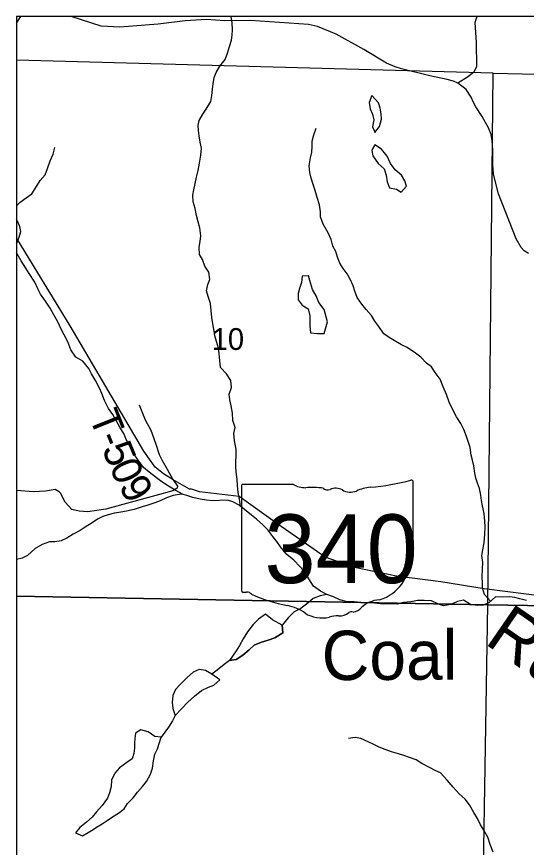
# Model space of a CAD drawing. Extents: x -452339 to 6403467, y -1 to 1814750.
# Drawn here: x -75201 to -70035, y 1554727 to 1563141 of the extents above; entities that cross this region are included whole.
import ezdxf

# ---------------------------------------------------------------- set-up
doc = ezdxf.new("R2010")
doc.units = 0
for name, color, linetype in [('Default', 7, 'Continuous'), ('GM_X_Corporation', 7, 'Continuous'), ('GM_X_County_Road', 7, 'Continuous'), ('GM_X_County_ROW', 7, 'Continuous'), ('GM_X_Major_Lake', 7, 'Continuous'), ('GM_X_Major_Lake_Text', 7, 'Continuous'), ('GM_X_Major_River_Text', 7, 'Continuous'), ('GM_X_Section_Text', 7, 'Continuous'), ('GM_X_Township_Road', 7, 'Continuous'), ('GM_X_Township_Road_Text', 7, 'Continuous'), ('GM_X_Unincorporated_Location', 7, 'Continuous')]:
    doc.layers.add(name, color=color, linetype=linetype)

msp = doc.modelspace()

# ---------------------------------------------------------------- linework, layer by layer
at = {"layer": 'Default'}
msp.add_lwpolyline([(-73615.1, 1558449.2), (-73570.7, 1558383.8), (-73572.9, 1558365.8), (-73619.2, 1558338.3), (-73789.7, 1558290.2), (-74050.5, 1558219), (-74295.2, 1558151.8), (-74479.5, 1558125.8), (-74567.4, 1558132.9), (-74641.2, 1558147.7), (-74708.3, 1558222.6), (-74755.3, 1558313.3), (-74769.1, 1558327.5), (-74808.8, 1558350), (-74907, 1558335.1), (-75031.1, 1558326.5), (-75200.9, 1558340.5)], dxfattribs=at)
at = {"layer": 'GM_X_County_Road'}
msp.add_line((-75200.9, 1563075.2), (-75158.8, 1563140.5), dxfattribs=at)
msp.add_lwpolyline([(-69611, 1557238.6), (-70462.9, 1557344.8), (-70901.9, 1557416.9), (-71352.9, 1557474.9), (-71776, 1557561.2), (-72072.9, 1557666.1), (-72553.3, 1558000.6), (-72946.4, 1558281.7), (-73174.2, 1558307.7), (-73347.2, 1558329.2), (-73429.2, 1558353.2), (-73447.7, 1558354), (-73615.1, 1558449.2), (-73713.1, 1558511.2), (-73797.3, 1558577.5), (-73913.1, 1558739.5), (-74659.5, 1560008.5), (-75200.9, 1560899.1)], dxfattribs=at)
at = {"layer": 'GM_X_County_ROW'}
for points in [[(-70015, 1560741.7), (-70057.1, 1560767.5), (-70089.3, 1560801.3), (-70138, 1560891.1), (-70317.1, 1561346.5), (-70352, 1561478.4), (-70368.5, 1561548.4), (-70375.1, 1561636.5), (-70374.2, 1561788.8), (-70382.9, 1561882.9), (-70393.3, 1561946.9), (-70419.8, 1562012.8), (-70482.6, 1562128.5), (-70547.3, 1562228.2), (-70571.6, 1562272.1), (-70595.9, 1562324), (-70646.4, 1562401.7), (-70674.6, 1562427.5), (-70730.9, 1562467.1), (-70773, 1562486.8), (-70839.1, 1562504.3), (-71015.3, 1562541), (-71301.6, 1562610.9), (-71365.7, 1562630.4), (-71452, 1562669.8), (-71682.8, 1562806.2), (-71963.8, 1562962.3), (-72153.6, 1563038.8), (-72244.3, 1563059), (-72831.9, 1563100.5), (-73095.7, 1563098.3), (-73275.6, 1563112.1), (-73491.5, 1563097.9), (-73767.3, 1563065.7), (-74155, 1563033.3), (-74342.9, 1563045.1), (-74648.1, 1563140.5)], [(-70531, 1563140.5), (-70539.6, 1563131.7), (-70559.3, 1563079.4), (-70545.8, 1562877.2), (-70540.1, 1562634.9), (-70567.7, 1562578.6), (-70631.3, 1562528), (-70730.9, 1562467.1)], [(-73615.1, 1558449.2), (-73671.1, 1558553.3), (-73723.1, 1558643.4), (-73753.1, 1558703.5), (-73791.2, 1558817.6), (-73837.2, 1558949.8), (-73895.2, 1559053.9), (-73957.3, 1559204.1)]]:
    msp.add_lwpolyline(points, dxfattribs=at)
at = {"layer": 'GM_X_Major_River_Text'}
for points in [[(-71602, 1562342), (-71627.8, 1562269.8), (-71617.6, 1562207.8), (-71593.4, 1562151.8), (-71581.2, 1562095.8), (-71595, 1562023.7), (-71578.9, 1561986.4)], [(-71578.9, 1561986.4), (-71570.9, 1561967.7), (-71523.1, 1562027.9), (-71503.3, 1562102.1), (-71505.5, 1562156.1), (-71515.6, 1562212.1), (-71533.8, 1562268.1), (-71602, 1562342)], [(-71593.3, 1561800.8), (-71602.3, 1561783.3), (-71590.1, 1561729.3), (-71537.9, 1561651.4), (-71475.8, 1561599.6), (-71455.6, 1561533.6), (-71447.4, 1561467.5), (-71423.2, 1561405.5), (-71353.2, 1561393.7), (-71303.1, 1561363.9)], [(-71303.1, 1561363.9), (-71249.3, 1561422.1), (-71267.5, 1561478.1), (-71301.7, 1561536.1), (-71365.8, 1561589.9), (-71412, 1561651.8), (-71446.2, 1561725.8), (-71504.4, 1561799.7), (-71572.5, 1561841.5), (-71593.3, 1561800.8)], [(-72085.4, 1560174), (-72138.7, 1560244.5), (-72167.1, 1560312.4), (-72201.5, 1560378.2), (-72221.9, 1560444.1), (-72244.4, 1560514), (-72308.3, 1560513.6), (-72315.8, 1560449.5), (-72333.4, 1560387.3), (-72347, 1560337.2), (-72346.5, 1560271.1), (-72308.2, 1560217.3), (-72248, 1560179.7), (-72229.6, 1560111.8), (-72229.2, 1560057.7), (-72230.9, 1560007.7), (-72224.4, 1559939.7), (-72152.5, 1559932.2), (-72083.1, 1559932.4)], [(-72083.1, 1559932.4), (-72051.7, 1560048.8), (-72085.4, 1560174)], [(-72510.1, 1556976.5), (-72609.3, 1557032.1), (-72677.6, 1557087.7), (-72751.1, 1557037.1), (-72802.7, 1556984.7), (-72862.1, 1556910.2), (-72905.5, 1556837.8), (-72942.9, 1556771.5), (-72974.5, 1556719.2), (-73044.7, 1556619.6)], [(-73044.7, 1556619.6), (-72974.9, 1556630.2), (-72907.3, 1556674.8), (-72845.8, 1556729.4), (-72792.2, 1556775.9), (-72718.6, 1556806.5), (-72652.8, 1556825.1), (-72583, 1556849.7), (-72503.5, 1556898.4), (-72510.1, 1556976.5)], [(-73223.5, 1556482), (-73287.7, 1556519.5), (-73349.7, 1556529), (-73413.4, 1556502.4), (-73471, 1556447.9), (-73542.3, 1556375.2), (-73589.9, 1556324.8), (-73619.3, 1556264.4), (-73624.8, 1556194.3), (-73616.3, 1556132.3), (-73595.8, 1556062.4)], [(-73595.8, 1556062.4), (-73466.1, 1556199.3), (-73398.6, 1556257.8), (-73327.1, 1556314.4), (-73255.5, 1556348.9), (-73203.7, 1556369.3), (-73142.2, 1556423.8), (-73223.5, 1556482)], [(-73737.1, 1555843), (-73799.1, 1555850.6), (-73869.3, 1555898.2), (-73943.3, 1555917.7), (-73995, 1555883.3), (-74004.6, 1555831.1), (-74006.3, 1555781.1), (-74005.9, 1555731), (-74011.5, 1555677), (-74031.1, 1555624.8), (-74084.8, 1555586.4), (-74158.3, 1555533.8), (-74205.8, 1555479.4), (-74239.3, 1555407.1), (-74242.8, 1555343), (-74258.3, 1555278.9), (-74279.9, 1555224.7), (-74335.3, 1555150.2), (-74392.8, 1555087.8), (-74436.3, 1555033.4), (-74491.9, 1554981), (-74559.4, 1554928.5), (-74604.9, 1554874.1), (-74534.8, 1554842.6), (-74457.3, 1554889.2), (-74426, 1554909.5)], [(-74426, 1554909.5), (-74391.7, 1554931.7), (-74334, 1554964.1), (-74282.3, 1554998.5), (-74228.7, 1555034.9), (-74167.1, 1555075.3), (-74111.4, 1555117.8), (-74075.9, 1555172.1), (-74018.4, 1555230.5), (-73974.8, 1555286.9), (-73925.3, 1555345.3), (-73885.7, 1555395.6), (-73844.3, 1555468), (-73822.8, 1555528.2), (-73813.3, 1555602.3), (-73799.8, 1555670.4), (-73774.2, 1555724.7), (-73737.1, 1555843)]]:
    msp.add_lwpolyline(points, dxfattribs=at)
at = {"layer": 'GM_X_Section_Text'}
msp.add_lwpolyline([(-65016.9, 1563140.5), (-75200.9, 1563140.5), (-75200.9, 1547985.7), (-65249.9, 1547985.7), (-65216.2, 1549772.3), (-65189.8, 1554406.9), (-65173, 1556706.7), (-65038.6, 1562427.1)], close=True, dxfattribs=at)
at = {"layer": 'GM_X_Township_Road'}
for p, q in [((-71183.1, 1557876.9), (-71183.1, 1558429.6)), ((-72923.3, 1558385.2), (-72923.3, 1557328.6)), ((-72396.6, 1558403.4), (-72906.2, 1558403.4)), ((-71183.3, 1557877), (-71183.1, 1557876.9))]:
    msp.add_line(p, q, dxfattribs=at)
for centre, major_axis, start_param, end_param in [((-71803, 1559844), (1845.5, 0), 4.814394, 5.042369), ((-71202.4, 1558431.9), (19.4, 0), 6.141152, 7.989035), ((-72903.4, 1558387.5), (20.2, 0), 1.712693, 3.28349), ((-72275.2, 1558526.1), (195.5, 0), 4.042523, 4.731795), ((-72210.4, 1557810.2), (702, 0), 1.404758, 1.657858), ((-72051, 1558393), (56.4, 0), 3.836095, 5.185415), ((-71968.2, 1558270.8), (117.3, 0), 0.950623, 2.079405), ((-71816.8, 1558438.4), (141.1, 0), 4.081561, 5.145723), ((-71567.6, 1558080.7), (371.3, 0), 1.699011, 2.107814), ((-71187.6, 1557836.3), (30, 0), 1.883978, 3.671073), ((-71203.8, 1557874.7), (20.7, 0), 5.05454, 6.418171), ((-71378.3, 1557766.4), (180, 0), 5.934695, 6.695948), ((-71113.7, 1557645.6), (130.9, 0), 2.387724, 3.262537), ((-71699.6, 1557575.2), (461.6, 0), 5.101752, 6.440018), ((-72903.2, 1557326.3), (20.3, 0), 3.00124, 4.508301), ((-72900.1, 1557434.4), (155.2, 0), 4.665946, 4.897461), ((-72868.4, 1557267.7), (56, 0), 0.519207, 1.627899), ((-72161.8, 1558217), (1332.7, 0), 4.195997, 4.488961), ((-72559.1, 1556853.9), (417, 0), 0.823519, 1.323587), ((-71825.3, 1557226.2), (149.1, 0), 4.937069, 5.64225), ((-71505, 1557032), (252.8, 0), 1.647645, 2.488434), ((-72108.1, 1557262.4), (264.6, 0), 4.026481, 4.996735), ((-71955.2, 1556897.1), (217.4, 0), 1.495662, 1.94098), ((-71935.9, 1557183.3), (141, 0), 4.691044, 5.507374), ((-71808.4, 1557080.9), (39.7, 0), 1.147584, 2.315152)]:
    msp.add_ellipse(centre, major_axis=major_axis, ratio=0.8, start_param=start_param, end_param=end_param, dxfattribs=at)
at = {"layer": 'GM_X_Township_Road_Text'}
for points in [[(-72932.1, 1558180.6), (-72941.9, 1558252.7), (-72954.4, 1558320.6), (-72961, 1558390.7), (-72967.5, 1558456.7), (-72976, 1558526.7), (-72978.5, 1558582.8), (-72978.9, 1558634.9), (-72977.4, 1558693), (-72975.9, 1558759.1), (-72994.6, 1558843), (-72999.1, 1558919.1), (-72987.6, 1558979.2), (-73010.2, 1559051.2), (-73012.8, 1559123.2), (-73027.3, 1559197.2), (-73041.8, 1559259.2), (-73048.3, 1559317.2), (-73022.8, 1559385.5), (-73031.4, 1559455.5), (-73073.9, 1559523.2), (-73134.3, 1559586.8), (-73142.9, 1559656.9), (-73147.4, 1559724.9), (-73153.9, 1559782.9), (-73176.4, 1559848.8), (-73192.8, 1559908.8), (-73201.4, 1559976.8), (-73211.8, 1560030.8), (-73224.3, 1560094.7), (-73230.8, 1560164.8), (-73237.4, 1560236.8), (-73259.9, 1560304.7), (-73278.4, 1560364.6), (-73262.9, 1560426.8), (-73243.3, 1560477), (-73253.9, 1560551), (-73294.3, 1560612.8), (-73318.9, 1560680.6), (-73349.2, 1560732.5), (-73351.8, 1560804.5), (-73340.3, 1560864.7), (-73334.7, 1560918.8), (-73343.4, 1561002.8), (-73361.9, 1561062.7), (-73378.3, 1561126.7), (-73392.9, 1561198.6), (-73413.4, 1561264.5), (-73415.9, 1561332.6), (-73404.4, 1561384.7), (-73379.4, 1561515.1), (-73362, 1561583.3), (-73348.6, 1561657.5), (-73333.2, 1561737.7), (-73327.8, 1561807.8), (-73340.3, 1561869.7), (-73350.8, 1561933.7), (-73357.2, 1561985.7), (-73361.6, 1562037.7), (-73350, 1562089.9), (-73314.5, 1562154.2), (-73279, 1562204.6), (-73233.6, 1562281), (-73224.1, 1562343.2), (-73216.6, 1562405.3), (-73209.1, 1562459.4), (-73197.6, 1562523.6), (-73178, 1562575.8), (-73142.6, 1562640.1), (-73089.1, 1562704.6), (-73063.7, 1562768.9), (-73042.2, 1562837.1), (-73022.7, 1562901.3), (-73015.1, 1562951.4), (-73013.6, 1563007.5), (-73018.1, 1563077.5), (-73028.5, 1563140.5)], [(-72093.8, 1561037.1), (-72121.5, 1561112.9), (-72121.9, 1561163), (-72130.4, 1561235), (-72155, 1561308.9), (-72175.6, 1561380.8), (-72196, 1561438.7), (-72216.5, 1561504.6), (-72230.9, 1561560.5), (-72237.5, 1561630.5), (-72222.1, 1561710.7), (-72208.6, 1561766.9), (-72207, 1561825), (-72207.5, 1561879), (-72188, 1561943.3), (-72166.5, 1562009.5)], [(-75200.9, 1561224.2), (-75163.7, 1561262.1), (-75104.1, 1561306.7), (-75046.4, 1561347.2), (-74999.1, 1561419.7), (-74961.6, 1561482), (-74910.1, 1561538.5), (-74886.6, 1561602.8), (-74861.2, 1561679.1), (-74829.8, 1561747.4), (-74812.4, 1561813.6)], [(-75200.9, 1560842), (-75196.4, 1560853.4), (-75174.8, 1560905.7), (-75159.3, 1560963.8), (-75167.7, 1561015.8), (-75192.1, 1561067.7), (-75200.9, 1561084.6)], [(-70398.6, 1557219.3), (-70461, 1557287), (-70481.2, 1557357), (-70481.3, 1557409.1), (-70483.5, 1557463.2), (-70479.8, 1557545.3), (-70476, 1557613.4), (-70486.2, 1557683.5), (-70478.4, 1557741.6), (-70464.6, 1557811.8), (-70456.9, 1557899.9), (-70453.1, 1557972), (-70455.3, 1558030.1), (-70463.5, 1558108.2), (-70479.7, 1558186.3), (-70489.9, 1558240.3), (-70496.1, 1558294.4), (-70510.3, 1558362.4), (-70532.4, 1558414.4), (-70548.6, 1558466.5), (-70556.7, 1558518.5), (-70567, 1558590.6), (-70581.1, 1558648.6), (-70595.3, 1558700.6), (-70605.5, 1558776.7), (-70621.7, 1558828.7), (-70641.8, 1558888.8), (-70670.1, 1558958.8), (-70700.2, 1559020.8), (-70742.4, 1559088.7), (-70776.6, 1559150.7), (-70816.8, 1559234.7), (-70845.1, 1559314.7), (-70877.3, 1559392.7), (-70909.5, 1559468.7), (-70959.7, 1559536.6), (-70997.9, 1559594.6), (-71048, 1559632.4), (-71104.1, 1559692.3), (-71160.2, 1559732.2), (-71244.4, 1559788), (-71300.4, 1559815.8), (-71376.5, 1559859.6), (-71426.6, 1559891.5), (-71480.7, 1559929.4), (-71528.9, 1560001.3), (-71571.1, 1560057.3), (-71603.2, 1560115.2), (-71659.4, 1560175.1), (-71701.5, 1560227), (-71751.7, 1560297), (-71773.9, 1560359), (-71792.1, 1560413), (-71820.3, 1560483), (-71850.4, 1560536.9), (-71890.6, 1560590.9), (-71924.7, 1560642.8), (-71950.9, 1560704.8), (-71967, 1560760.8), (-71997.2, 1560816.8), (-72013.4, 1560884.8), (-72045.6, 1560950.8), (-72093.8, 1561037.1)], [(-73513.9, 1558299.4), (-73594, 1558343.4), (-73660.2, 1558384.9), (-73728.5, 1558428.4), (-73784.8, 1558470), (-73859.2, 1558525.5), (-73913.5, 1558573.1), (-73968, 1558648.8), (-74018.6, 1558722.5), (-74047, 1558776.3), (-74091.6, 1558858), (-74112, 1558911.9), (-74154.5, 1558981.7), (-74225.5, 1559111.3), (-74269.9, 1559171), (-74310.5, 1559252.8), (-74337.1, 1559324.6), (-74361.5, 1559378.5), (-74400, 1559454.3), (-74440.5, 1559524), (-74468.9, 1559575.9), (-74529.5, 1559649.5), (-74599.7, 1559690.9), (-74652.3, 1559764.6), (-74682.9, 1559846.5), (-74717.4, 1559916.3), (-74749.8, 1559976.1), (-74784.4, 1560049.9), (-74824.9, 1560119.6), (-74861.4, 1560187.4), (-74907.9, 1560257.1), (-74960.5, 1560330.8), (-74986.9, 1560384.6), (-75015.4, 1560452.4), (-75074, 1560540.1), (-75108.4, 1560591.9), (-75154.9, 1560667.6), (-75195.4, 1560737.3), (-75200.9, 1560752.4)], [(-72057.2, 1557286.6), (-72123.3, 1557322.1), (-72193.6, 1557373.6), (-72240.2, 1557447.3), (-72276.6, 1557511.1), (-72329, 1557568.7), (-72393.5, 1557636.3), (-72461.9, 1557693.8), (-72528.5, 1557771.4), (-72564.8, 1557823.2), (-72603.2, 1557874.9), (-72655.7, 1557942.6), (-72706.1, 1557994.2), (-72768.5, 1558051.8), (-72820.7, 1558091.4), (-72891.1, 1558148.9), (-72947.4, 1558192.5), (-73009.6, 1558226.1), (-73063.7, 1558243.6), (-73145.6, 1558239), (-73211.5, 1558236.4), (-73275.5, 1558241.9), (-73341.5, 1558253.4), (-73413.6, 1558270.8), (-73477.7, 1558290.3), (-73531.7, 1558303.9), (-73615.5, 1558291.2), (-73681.3, 1558266.6), (-73745, 1558238.1), (-73798.8, 1558217.6), (-73870.5, 1558193), (-73930.3, 1558174.5), (-74010, 1558147.8), (-74087.8, 1558131.1), (-74145.6, 1558120.6), (-74207.5, 1558112.1), (-74273.3, 1558095.5), (-74327.1, 1558079.1), (-74382.9, 1558050.6), (-74436.5, 1558014.1), (-74506.1, 1557969.5), (-74557.8, 1557935), (-74629.4, 1557900.3), (-74693, 1557857.8), (-74748.7, 1557831.3), (-74814.6, 1557822.7), (-74868.5, 1557820.3), (-74940.3, 1557795.7), (-75013.9, 1557753), (-75091.2, 1557682.3), (-75144.9, 1557655.8), (-75200.9, 1557644.1)], [(-72057.2, 1557286.6), (-72124.9, 1557274), (-72196.6, 1557247.4), (-72248.2, 1557204.9), (-72319.7, 1557146.2), (-72387.3, 1557111.6), (-72450.8, 1557051), (-72510.1, 1556976.5), (-72503.5, 1556898.4), (-72583, 1556849.7), (-72652.8, 1556825.1), (-72718.6, 1556806.5), (-72792.2, 1556775.9), (-72845.8, 1556729.4), (-72907.3, 1556674.8), (-72974.9, 1556630.2), (-73044.7, 1556619.6), (-73096.4, 1556579.1), (-73169.8, 1556522.5), (-73223.5, 1556482), (-73287.7, 1556519.5), (-73349.7, 1556529), (-73413.4, 1556502.4), (-73471, 1556447.9), (-73542.3, 1556375.2), (-73589.9, 1556324.8), (-73619.3, 1556264.4), (-73624.8, 1556194.3), (-73616.3, 1556132.3), (-73595.8, 1556062.4), (-73621.3, 1556008.1), (-73662.7, 1555943.7), (-73737.1, 1555843)], [(-70033, 1557226.4), (-70101, 1557244.1), (-70151, 1557258), (-70205, 1557263.8), (-70277, 1557261.6), (-70347, 1557265.3), (-70414.7, 1557205), (-70472.6, 1557180.8), (-70530.6, 1557176.6), (-70602.6, 1557188.3), (-70672.7, 1557230.2), (-70734.7, 1557217.9), (-70800.5, 1557185.6), (-70876.5, 1557173.4), (-70926.5, 1557191.2), (-70996.6, 1557223), (-71070.5, 1557226.8), (-71138.5, 1557228.6), (-71206.4, 1557212.3), (-71280.4, 1557208), (-71346.3, 1557191.8), (-71424.3, 1557193.5), (-71486.3, 1557191.3), (-71548.3, 1557197.1), (-71600.3, 1557204.9), (-71658.2, 1557200.7), (-71714.2, 1557206.5), (-71784.2, 1557214.3), (-71860.2, 1557218.1), (-71924.2, 1557233.9), (-71988.3, 1557263.7), (-72057.2, 1557286.6)], [(-70373, 1554679.6), (-70403.2, 1554755.6), (-70427.4, 1554831.6), (-70465.6, 1554901.5), (-70501.8, 1554955.5), (-70532, 1555019.5), (-70568.1, 1555081.4), (-70610.3, 1555157.4), (-70656.5, 1555215.3), (-70716.7, 1555269.2), (-70778.8, 1555337), (-70839, 1555408.9), (-70907.2, 1555480.8), (-70959.3, 1555506.7), (-71017.4, 1555536.5), (-71095.4, 1555576.3), (-71153.5, 1555612.1), (-71219.6, 1555637.9), (-71277.6, 1555657.8), (-71329.6, 1555673.6), (-71401.7, 1555695.4), (-71465.7, 1555719.2), (-71525.8, 1555743), (-71581.8, 1555768.9), (-71639.9, 1555796.7), (-71712, 1555830.5), (-71770, 1555840.3), (-71837.9, 1555830.1)]]:
    msp.add_lwpolyline(points, dxfattribs=at)
at = {"layer": 'GM_X_Unincorporated_Location'}
for points in [[(-75200.9, 1562701), (-75200.9, 1557272.8), (-70427.3, 1557184.9), (-70371.2, 1562567.6)], [(-65059.8, 1562444.8), (-65186.4, 1557097.3), (-70427.3, 1557184.9), (-70371.2, 1562567.6)], [(-75200.9, 1557272.8), (-75200.9, 1551940.1), (-70513.9, 1551851.8), (-70427.3, 1557184.9)], [(-70427.3, 1557184.9), (-65186.4, 1557097.3), (-65238.6, 1551724.6), (-70513.9, 1551851.8)]]:
    msp.add_lwpolyline(points, close=True, dxfattribs=at)

# ---------------------------------------------------------------- texts
at = {"layer": 'GM_X_Corporation'}
for s, height, rotation, p in [('Run', 500.11, 325.43818, (-70472.2, 1556798)), ('Coal', 499.98, 0.24301, (-72108.8, 1556420.8))]:
    msp.add_text(s, height=height, rotation=rotation, dxfattribs=at).set_placement(p)
at = {"layer": 'GM_X_Major_Lake'}
msp.add_text('10', height=220.83, rotation=0.00001, dxfattribs=at).set_placement((-73224.5, 1559764.8))
at = {"layer": 'GM_X_Major_Lake_Text'}
for s, rotation, p in [('T', 291.88736, (-74471.1, 1559089.2)), ('5', 292.34872, (-74340.4, 1558764.3)), ('-', 291.97357, (-74387.3, 1558880.5)), ('0', 294.21811, (-74265.9, 1558583.5)), ('9', 300.74211, (-74172.9, 1558382))]:
    msp.add_text(s, height=300, rotation=rotation, dxfattribs=at).set_placement(p)
at = {"layer": 'GM_X_Township_Road'}
msp.add_text('340', height=696.1, dxfattribs=at).set_placement((-72689.2, 1557403.1))

doc.saveas('drawing.dxf')
